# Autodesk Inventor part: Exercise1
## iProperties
Shininess: 77.0
Length Units: 11269
Angle Units: 11279
Time Units: 11290
Mass Units: 11283
Length Display Precision: 3
Angle Display Precision: 2
Created: 2001-11
Part Number: Exercise1
Document SubType Name: Modeling
Designer: Renu Muthoo
Density: 1 g/cm^3
Density: 0.0
Volumn: 0.0
Area: 0.0
PropertySet Name: Model Information
Control State: 0
Master: False
Checked Out: False
Author: Renu Muthoo
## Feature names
1. Extrusion1
2. Extrusion2
3. Extrusion3
4. Extrusion4
